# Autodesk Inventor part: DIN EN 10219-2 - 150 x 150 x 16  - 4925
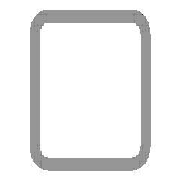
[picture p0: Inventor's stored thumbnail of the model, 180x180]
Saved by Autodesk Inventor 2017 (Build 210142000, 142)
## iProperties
IsCustomPart: 1
Created: 2017-11
Part Number: DIN EN 10219-2 - 150 x 150 x 16  - 4925
Material: Steel, Mild
Description: Cold formed welded structural hollow sections of non-alloy and fine grain structural steel
Document SubType Name: Modeling
Standard: DIN
Designer: iusti
Standard Revision: 2006-07
Standards Organization: DIN
Language: en-US
Size Designation: 150 x 150 x 16
Categories: <MemberInstance><Categories><Category DisplayName="Structural Shapes" InternalName="089c4875-fa83-4c05-b084-43b9cc11f5ed" Mnemonic="GRDR"><CategoryParameter Dis
Stock Number: 150 x 150 x 16
Density: 7.85 g/cm^3
Appearance: Semi-Polished
Mass: 289079 g
Surface Area: 46181.3 cm^2
Volume: 36825.4 cm^3
_CCFamilyMember: 76
_CCFamilyDisplayName: DIN EN 10219-2 (Square Hollow Section - Cold Formed) - Cold formed welded structural hollow sections of non-alloy and fine grain structural steel
_FrameMemberDoc: Frame Member File
_Version: 15.0.0
_GetPNFromCC: 1
G_L: 4925.000 mm
G_W: 150.000 mm
G_H: 150.000 mm
+6FBBBA41-A689-4153-B866-6340EAF31301+CUTDETAIL1: Cut
Author: iusti
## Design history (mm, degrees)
node "Start plane"
node "End plane"
sketch "Sketch"
  geometry: L1 (-75, -27)-(-75, 27); L2 (-27, 75)-(27, 75); L3 (75, 27)-(75, -27); L4 (27, -75)-(-27, -75); L5 (-27, 59)-(27, 59); L6 (59, 27)-(59, -27); L7 (27, -59)-(-27, -59); L8 (-59, -27)-(-59, 27); L9 (0, 118.918)-(0, -118.918) reference; L10 (-118.918, 0)-(118.918, 0) reference; A1 r 48 centre (-27, -27) between (-75, -27) and (-27, -75); A2 r 48 centre (-27, 27) between (-27, 75) and (-75, 27); A3 r 48 centre (27, 27) between (75, 27) and (27, 75); A4 r 48 centre (27, -27) between (27, -75) and (75, -27); A5 r 32 centre (-27, 27) between (-27, 59) and (-59, 27); A6 r 32 centre (27, 27) between (59, 27) and (27, 59); A7 r 32 centre (27, -27) between (27, -59) and (59, -27); A8 r 32 centre (-27, -27) between (-59, -27) and (-27, -59)
  constraints: 16 end point, 16 point on circle, 8 centre point, 8 tangent, 4 parallel, 3 equal radius, 2 perpendicular, 7 other
  dimensions: "d7" = 48 radius of A1 (= G_IR); "d10" = 150 distance between parallel lines of L2 L4 (= G_H); "d11" = 150 distance between parallel lines of L1 L3 (= G_W); "d12" = 16 distance between parallel lines of L3 L6 (= G_T); "d15" = 75 distance between parallel lines of L2 L10 (= 0.5 x d10); "d16" = 75 distance between parallel lines of L9 L3 (= 0.5 x d11)
extrude "Body" new body sketch "Sketch" stored distance "d3" = 4925 (= G_L); taper "d4" = 0 deg
node "Driven Length"
  sketch "Sketch3"
    geometry: L1 (0, 0)-(10, 0) reference
    constraints: 2 end point, 1 horizontal
  workplane "Work Plane3"
  sketch "Sketch4"
    geometry: L1 (-2, 0)-(12, 0) reference; L2 (-2, 4925)-(12, 4925) reference
    dimensions: "d18" = 4925 distance between parallel lines of L1 L2 (derived)
workplane "Work Plane4"
split "Split1"
body "Solid1"
other parameters: "G_W" = 150 [user parameter; used in 1 equation term], "G_H" = 150 [user parameter; used in 1 equation term], "G_T" = 16 [user parameter; used in 1 equation term], "G_IR" = 48 [user parameter; used in 1 equation term], "G_L" = 4925 (= d18) [user parameter; used in 1 equation term], "G_OFFSET_START" = 0 [user parameter; used in 1 equation term], "G_OFFSET_END" = -75 [user parameter; used in 1 equation term], "d13" = 0 (computed from G_OFFSET_START), "d14" = 4925 (= G_OFFSET_END + B_L), "d17" = 90 deg
